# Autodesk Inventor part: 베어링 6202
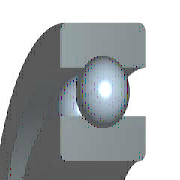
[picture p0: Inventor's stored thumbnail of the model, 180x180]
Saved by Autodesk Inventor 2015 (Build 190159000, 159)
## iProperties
IsCustomPart: 1
Created: 2015-09
Part Number: 베어링 6202
Material: 강철, 연강
Description: 깊은 그루브 볼 베어링
Document SubType Name: Modeling
Standard: KS B 2023
Designer: mduedu
Standards Organization: KS
Language: ko-KR
Size Designation: 6202 - 15 x 35 x 11
Categories: <MemberInstance><Categories><Category DisplayName="샤프트 부품" InternalName="7f7aeb1f-a693-4053-b835-cee3144e0d98" Mnemonic="SHFT"><Category DisplayName="베어링" Inter
Density: 7.86 g/cm^3
Mass: 45.8725 g
Surface Area: 51.5584 cm^2
Volume: 5.83619 cm^3
Appearance: 노란색
Author: mduedu
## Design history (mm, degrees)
sketch "스케치" dims "d0" = 5.2 (= -0.26 x WD + 0.26 x BD)
  geometry: L1 (2.9, 12.5)-(8.1, 12.5); L2 (5.5, 12.5)-(5.5, 9.9); L3 (5.5, 12.5)-(5.5, 15.1); L4 (3.568, 10.76)-(0, 10.76); L5 (0, 7.5)-(11, 7.5); L6 (3.568, 14.24)-(0, 14.24); L7 (0, 17.5)-(11, 17.5); L8 (11, 7.5)-(11, 10.76); L9 (7.432, 10.76)-(11, 10.76); L10 (7.432, 14.24)-(11, 14.24); L11 (11, 17.5)-(11, 14.24); L12 (-1.4, 0)-(8.4, 0) reference; L13 (0, -0.3)-(0, 5.3) reference
  constraints: 22 end point, 4 point on line, 2 collinear, 2 perpendicular, 2 symmetric about line, 1 midpoint, 1 parallel, 14 other
  dimensions: "d9" = 15 diameter of L5 L12 (= WD); "d11" = 35 diameter of L7 L12 (= BD); "d12" = 11 distance between parallel lines of L8 L13 (= KB); "d13" = 21.52 diameter of L9 L12 (= 0.326 x BD + 0.674 x WD)
revolve "본체" stored, may be unused: angle "d6" = 90 deg
revolve "볼" stored, may be unused: angle "d7" = 90 deg
pattern_circular "IDS_ARRAYBALL[SIMPL:T]" dims angle "d3" = 360 deg
body "Solid1"
fillet "모깎기1" dims "d1" = 0.6 (= KRS)
other parameters: "WD" = 15 [user parameter; used in 5 equation terms], "BD" = 35 [user parameter; used in 5 equation terms], "KB" = 11 [user parameter; used in 1 equation term], "KRS" = 0.6 [user parameter; used in 1 equation term], "d4" = 0, "d5" = 0, "d8" = 0, "d14" = 0, "d15" = 0, "BBA" = 0 [user parameter], "BC0" = 3750000 [user parameter], "BC" = 7800000 [user parameter], "BR" = 17.5 (= 0.5 x BD) [user parameter], "WR" = 7.5 (= 0.5 x WD) [user parameter]
